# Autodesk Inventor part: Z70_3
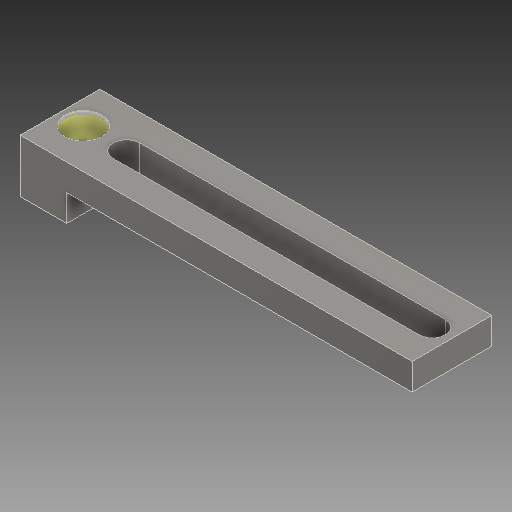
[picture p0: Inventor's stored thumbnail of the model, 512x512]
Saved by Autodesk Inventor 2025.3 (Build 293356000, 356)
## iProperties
Created: 2025-03
Part Number: Z70_3
Material: Všeobecné
Document SubType Name: Modeling
Designer: Patrik
Density: 1 g/cm^3
Appearance: Výchozí
Mass: 280.884 g
Surface Area: 565.051 cm^2
Volume: 280.884 cm^3
Author: Patrik
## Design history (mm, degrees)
feature "Base1"
node "Těleso1"
